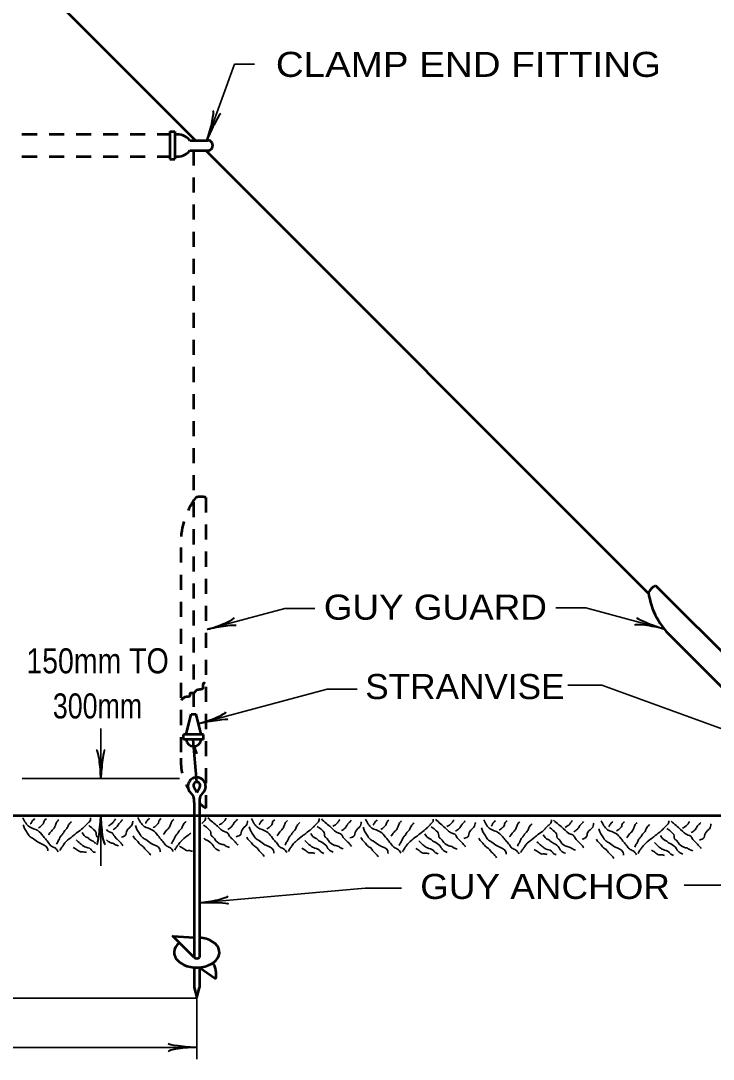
# Model space of a CAD drawing. Extents: x 14808 to 15663, y 10944 to 11488.
# Drawn here: x 15352 to 15435, y 11248.2 to 11372.5 of the extents above; entities that cross this region are included whole.
import ezdxf
from ezdxf.enums import TextEntityAlignment as Align

# ---------------------------------------------------------------- set-up
doc = ezdxf.new("R2010")
doc.units = 0
doc.header["$LTSCALE"] = 1.2
doc.linetypes.add('SHORT_DASHED', pattern=[2.7, 1.5, -1.2])
doc.layers.add('1', color=7, linetype='Continuous', lineweight=53)

msp = doc.modelspace()

# ---------------------------------------------------------------- linework, layer by layer
at = {"layer": '1'}
for p, q in [((15299.491, 11431.696), (15372.897, 11358.29)), ((15369.889, 11359.262), (15369.889, 11355.963)), ((15369.889, 11359.262), (15370.489, 11359.262)), ((15370.489, 11359.262), (15370.489, 11355.963)), ((15372.303, 11358.217), (15374.389, 11358.213)), ((15372.303, 11357.004), (15374.483, 11357.013)), ((15374.159, 11357.028), (15427.228, 11303.959)), ((15369.889, 11355.963), (15370.489, 11355.963)), ((15428.058, 11304.925), (15454.362, 11278.621)), ((15430.179, 11298.561), (15447.998, 11280.742)), ((15371.835, 11287.093), (15372.435, 11289.493)), ((15372.435, 11289.493), (15373.034, 11289.493)), ((15373.635, 11287.093), (15373.034, 11289.493)), ((15373.934, 11287.093), (15371.535, 11287.093)), ((15371.535, 11286.493), (15371.535, 11287.093)), ((15373.934, 11286.493), (15373.934, 11287.093)), ((15373.934, 11286.493), (15371.535, 11286.493)), ((15373.128, 11281.388), (15372.681, 11286.489)), ((15372.753, 11285.671), (15373.087, 11284.754)), ((15373.118, 11280.128), (15372.758, 11280.752)), ((15373.118, 11280.128), (15373.478, 11280.752)), ((15373.427, 11278.945), (15373.427, 11272.659)), ((15267.529, 11277.361), (15491.726, 11277.361)), ((15373.427, 11272.61), (15373.427, 11260.378)), ((15373.427, 11259.178), (15373.427, 11256.778)), ((15373.427, 11259.178), (15375.393, 11257.801))]:
    msp.add_line(p, q, dxfattribs=at)
at = {"layer": '1', "linetype": 'SHORT_DASHED'}
for p, q in [((15297.1, 11358.975), (15369.889, 11358.975)), ((15372.735, 11357.006), (15372.735, 11289.493)), ((15297.101, 11356.276), (15369.889, 11356.276)), ((15374.202, 11315.454), (15374.202, 11278.254)), ((15371.203, 11309.454), (15371.203, 11284.254))]:
    msp.add_line(p, q, dxfattribs=at)
at = {"layer": '1', "lineweight": 35}
for p, q in [((15383.661, 11302.157), (15374.388, 11299.673)), ((15383.661, 11302.157), (15387.261, 11302.157)), ((15419.732, 11302.225), (15416.132, 11302.225)), ((15429.004, 11299.741), (15419.732, 11302.225)), ((15388.739, 11292.497), (15373.398, 11288.387)), ((15388.739, 11292.497), (15392.313, 11292.497)), ((15421.629, 11293.001), (15417.559, 11293.001)), ((15445.843, 11284.188), (15421.629, 11293.001)), ((15361.621, 11281.805), (15361.621, 11287.805)), ((15371.052, 11281.805), (15352.19, 11281.805)), ((15361.621, 11277.361), (15361.621, 11271.361)), ((15393.276, 11268.659), (15373.427, 11266.923)), ((15393.276, 11268.659), (15397.622, 11268.659)), ((15436.634, 11269.019), (15431.481, 11269.019)), ((15373.088, 11255.52), (15350.104, 11255.52)), ((15373.106, 11255.474), (15373.106, 11248.194)), ((15296.404, 11249.616), (15373.132, 11249.616))]:
    msp.add_line(p, q, dxfattribs=at)
msp.add_lwpolyline([(15374.36, 11358.317), (15377.643, 11367.338), (15380.043, 11367.338)], dxfattribs=at)
at = {"layer": '1'}
for points in [[(15372.8, 11278.945), (15372.8, 11272.61), (15372.8, 11260.378)], [(15372.8, 11260.378), (15370.254, 11262.923), (15372.784, 11262.764)], [(15372.8, 11259.178), (15372.8, 11256.778), (15373.113, 11255.578), (15373.427, 11256.778)]]:
    msp.add_lwpolyline(points, dxfattribs=at)
for centre, radius, start, end in [((15370.75, 11356.916), 2.026, 39.94521, 97.50756), ((15374.436, 11357.613), 0.602, 265.53287, 94.46714), ((15370.75, 11358.306), 2.026, 262.49244, 320.05479), ((15428.876, 11303.258), 1.858, 116.15616, 153.84384), ((15436.389, 11305.462), 9.284, 188.58388, 228.01714), ((15372.734, 11286.575), 0.904, 185.20411, 354.79589), ((15373.119, 11280.881), 1.064, 337.37581, 202.62419), ((15373.118, 11280.968), 0.42, 328.9871, 211.0129), ((15375.089, 11281.959), 3.305, 206.74116, 223.96028), ((15371.043, 11279.091), 1.762, 355.24577, 19.00426), ((15375.184, 11279.091), 1.762, 160.99574, 184.75423), ((15371.61, 11281.661), 2.761, 313.69833, 334.49446), ((15373.113, 11260.715), 0.461, 227.04039, 312.95961), ((15372.947, 11258.344), 2.506, 347.48706, 33.42981)]:
    msp.add_arc(centre, radius, start, end, dxfattribs=at)
at = {"layer": '1', "linetype": 'SHORT_DASHED'}
for centre, radius, start, end in [((15373.602, 11313.696), 1.858, 71.15616, 108.84384), ((15380.473, 11309.943), 9.284, 143.58388, 183.01714), ((15378.192, 11283.999), 6.994, 177.90975, 209.56823), ((15378.192, 11283.999), 6.994, 227.0576, 235.22035)]:
    msp.add_arc(centre, radius, start, end, dxfattribs=at)
at = {"layer": '1', "lineweight": 40}
for centre, major_axis, ratio, start_param, end_param in [((15374.496, 11359.661), (-0.557, -2.078), 0.122415, 0.8963533, 3.1415927), ((15375.058, 11359.494), (0.919, 1.909), 0.07063, 6.2823074, 8.5597026), ((15375.567, 11300.332), (-2.021, -0.736), 0.122415, 0.8963533, 3.1415927), ((15427.771, 11300.334), (-1.981, 0.749), 0.07063, 6.2823074, 8.5597026), ((15375.753, 11299.776), (2.09, 0.342), 0.07063, 6.2823074, 8.5597026), ((15427.654, 11299.759), (2.118, -0.374), 0.122415, 0.8963533, 3.1415927), ((15374.577, 11289.046), (-2.021, -0.736), 0.122415, 0.8963533, 3.1415927), ((15374.763, 11288.489), (2.09, 0.342), 0.07063, 6.2823074, 8.5597026), ((15361.289, 11283.114), (0.187, -2.143), 0.122415, 0.8963533, 3.1415927), ((15361.875, 11283.15), (0.211, 2.108), 0.07063, 6.2823074, 8.5597026), ((15361.367, 11276.017), (-0.211, -2.108), 0.07063, 6.2823074, 8.5597026), ((15361.952, 11276.052), (-0.187, 2.143), 0.122415, 0.8963533, 3.1415927), ((15374.703, 11267.367), (-2.118, -0.373), 0.122415, 0.8963533, 3.1415927), ((15374.789, 11266.787), (2.118, -0.026), 0.07063, 6.2823074, 8.5597026), ((15371.787, 11249.87), (2.108, -0.211), 0.07063, 3.1407148, 5.41811), ((15371.822, 11249.284), (2.143, 0.187), 0.122415, 0.8963533, 3.1415927)]:
    msp.add_ellipse(centre, major_axis=major_axis, ratio=ratio, start_param=start_param, end_param=end_param, dxfattribs=at)
at = {"layer": '1'}
msp.add_ellipse((15373.113, 11260.978), major_axis=(-2.714, 0), ratio=0.663245, start_param=5.5824837, end_param=10.8796755, dxfattribs=at)
msp.add_spline([(15374.123, 11293.2), (15373.921, 11293.218), (15373.842, 11292.771), (15373.792, 11292.539), (15373.376, 11292.444), (15372.918, 11292.214), (15372.726, 11292.034), (15372.301, 11291.994), (15372.274, 11291.688), (15371.871, 11291.572), (15371.521, 11291.447), (15371.238, 11291.148)], degree=3, dxfattribs=at)
at = {"layer": '1', "lineweight": 35}
for points in [[(15352.297, 11277.1), (15353.065, 11276.025), (15354.063, 11275.565), (15354.677, 11274.95), (15354.984, 11274.567), (15355.368, 11274.106), (15355.675, 11273.722), (15356.136, 11273.492), (15356.52, 11273.031)], [(15353.679, 11277.014), (15353.564, 11276.861), (15353.526, 11276.861), (15353.449, 11276.784), (15353.257, 11276.438), (15353.219, 11276.362)], [(15360.397, 11277.1), (15360.397, 11276.947), (15360.32, 11276.716), (15360.167, 11276.563), (15360.013, 11276.409), (15359.706, 11276.102), (15359.476, 11275.872), (15358.785, 11275.334), (15358.401, 11275.027), (15357.633, 11274.413), (15357.326, 11274.106), (15357.172, 11273.876), (15356.942, 11273.569), (15356.712, 11273.185)], [(15366.059, 11277.15), (15366.827, 11276.075), (15367.825, 11275.614), (15368.439, 11275), (15368.746, 11274.616), (15369.13, 11274.155), (15369.437, 11273.772), (15369.898, 11273.541), (15370.281, 11273.081)], [(15367.441, 11277.064), (15367.326, 11276.91), (15367.287, 11276.91), (15367.21, 11276.833), (15367.018, 11276.488), (15366.98, 11276.411)], [(15368.861, 11277.025), (15368.631, 11276.833), (15368.554, 11276.641), (15368.477, 11276.411), (15368.324, 11276.257), (15368.247, 11276.181), (15367.901, 11275.912)], [(15374.158, 11277.15), (15374.158, 11276.996), (15374.082, 11276.766), (15373.928, 11276.612), (15373.775, 11276.459), (15373.751, 11276.435)], [(15374.427, 11277.111), (15375.041, 11276.574), (15375.579, 11276.113), (15376.5, 11275.422), (15376.73, 11275.345), (15376.961, 11275.038), (15377.345, 11274.578), (15377.805, 11274.117), (15378.035, 11273.81)], [(15375.809, 11276.257), (15376.347, 11276.641), (15376.462, 11276.795), (15376.654, 11277.064)], [(15352.326, 11276.28), (15352.479, 11275.819), (15352.786, 11275.32), (15353.17, 11274.821), (15353.554, 11274.591), (15354.206, 11274.13), (15355.243, 11273.439), (15355.281, 11273.132)], [(15355.099, 11276.976), (15354.869, 11276.784), (15354.792, 11276.592), (15354.716, 11276.362), (15354.562, 11276.208), (15354.485, 11276.131), (15354.14, 11275.862)], [(15356.597, 11276.861), (15356.366, 11276.63), (15356.213, 11276.246), (15356.021, 11275.863), (15355.598, 11275.402), (15355.445, 11275.172), (15355.368, 11275.056)], [(15358.094, 11276.63), (15357.748, 11276.246), (15357.556, 11275.824), (15357.249, 11275.479), (15357.019, 11275.133), (15356.788, 11274.864), (15356.673, 11274.596), (15356.52, 11274.327), (15356.328, 11273.943)], [(15360.167, 11276.169), (15360.397, 11276.016), (15360.627, 11275.824), (15361.049, 11275.287), (15361.088, 11274.941), (15361.297, 11274.758)], [(15362.543, 11276.158), (15363.08, 11276.542), (15363.195, 11276.696), (15363.387, 11276.965)], [(15363.084, 11275.671), (15363.506, 11275.978), (15363.775, 11276.362), (15363.852, 11276.477), (15364.005, 11276.63), (15364.236, 11276.899)], [(15364.082, 11274.788), (15364.619, 11275.095), (15364.696, 11275.44), (15365.195, 11276.054), (15365.349, 11276.246), (15365.426, 11276.553), (15365.464, 11276.707)], [(15365.79, 11276.181), (15365.944, 11275.72), (15366.251, 11275.221), (15366.635, 11274.722), (15367.018, 11274.492), (15367.671, 11274.031), (15368.708, 11273.34), (15368.746, 11273.033)], [(15370.358, 11276.91), (15370.128, 11276.68), (15369.974, 11276.296), (15369.782, 11275.912), (15369.36, 11275.451), (15369.207, 11275.221), (15369.13, 11275.106)], [(15371.855, 11276.68), (15371.51, 11276.296), (15371.318, 11275.873), (15371.011, 11275.528), (15370.78, 11275.183), (15370.55, 11274.914), (15370.435, 11274.645), (15370.281, 11274.376), (15370.089, 11273.993)], [(15373.928, 11276.219), (15374.158, 11276.066), (15374.389, 11275.874), (15374.811, 11275.336), (15374.849, 11274.991), (15375.157, 11274.722), (15375.272, 11274.53), (15376.039, 11273.954), (15376.5, 11273.801), (15376.615, 11273.724), (15377.037, 11273.532)], [(15376.846, 11275.72), (15377.268, 11276.027), (15377.537, 11276.411), (15377.613, 11276.526), (15377.767, 11276.68), (15377.997, 11276.948)], [(15377.844, 11274.837), (15378.381, 11275.144), (15378.458, 11275.49), (15378.957, 11276.104), (15379.11, 11276.296), (15379.187, 11276.603), (15379.226, 11276.757)], [(15379.403, 11276.032), (15379.557, 11275.572), (15379.864, 11275.073), (15380.248, 11274.574), (15380.632, 11274.343), (15381.284, 11273.882), (15382.321, 11273.192), (15382.359, 11272.884)], [(15379.672, 11277.001), (15380.44, 11275.926), (15381.438, 11275.466), (15382.052, 11274.851), (15382.359, 11274.468), (15382.743, 11274.007), (15383.05, 11273.623), (15383.511, 11273.393), (15383.895, 11272.932)], [(15381.054, 11276.915), (15380.939, 11276.762), (15380.9, 11276.762), (15380.824, 11276.685), (15380.632, 11276.339), (15380.593, 11276.263)], [(15382.474, 11276.877), (15382.244, 11276.685), (15382.167, 11276.493), (15382.09, 11276.263), (15381.937, 11276.109), (15381.86, 11276.032), (15381.514, 11275.763)], [(15383.971, 11276.762), (15383.741, 11276.531), (15383.587, 11276.147), (15383.395, 11275.764), (15382.973, 11275.303), (15382.82, 11275.073), (15382.743, 11274.957)], [(15385.468, 11276.531), (15385.123, 11276.147), (15384.931, 11275.725), (15384.624, 11275.38), (15384.394, 11275.034), (15384.163, 11274.765), (15384.048, 11274.497), (15383.894, 11274.228), (15383.703, 11273.844)], [(15387.772, 11277.001), (15387.772, 11276.848), (15387.695, 11276.617), (15387.541, 11276.464), (15387.388, 11276.31), (15387.081, 11276.003), (15386.85, 11275.773), (15386.159, 11275.235), (15385.775, 11274.928), (15385.008, 11274.314), (15384.701, 11274.007), (15384.547, 11273.777), (15384.317, 11273.47), (15384.086, 11273.086)], [(15387.541, 11276.07), (15387.772, 11275.917), (15388.002, 11275.725), (15388.424, 11275.188), (15388.463, 11274.842), (15388.77, 11274.574), (15388.885, 11274.382), (15389.653, 11273.806), (15390.113, 11273.652), (15390.228, 11273.575), (15390.651, 11273.383)], [(15388.04, 11276.963), (15388.654, 11276.425), (15389.192, 11275.965), (15390.113, 11275.274), (15390.343, 11275.197), (15390.574, 11274.89), (15390.958, 11274.429), (15391.418, 11273.969), (15391.649, 11273.661)], [(15389.422, 11276.109), (15389.96, 11276.493), (15390.075, 11276.646), (15390.267, 11276.915)], [(15390.459, 11275.572), (15390.881, 11275.879), (15391.15, 11276.263), (15391.226, 11276.378), (15391.38, 11276.531), (15391.61, 11276.8)], [(15391.457, 11274.689), (15391.994, 11274.996), (15392.071, 11275.341), (15392.57, 11275.955), (15392.723, 11276.147), (15392.8, 11276.454), (15392.839, 11276.608)], [(15393.066, 11275.983), (15393.219, 11275.522), (15393.526, 11275.023), (15393.91, 11274.524), (15394.294, 11274.294), (15394.947, 11273.833), (15395.983, 11273.142), (15396.022, 11272.835)], [(15393.335, 11276.952), (15394.102, 11275.877), (15395.1, 11275.416), (15395.715, 11274.802), (15396.022, 11274.418), (15396.406, 11273.957), (15396.713, 11273.574), (15397.173, 11273.343), (15397.557, 11272.882)], [(15394.716, 11276.866), (15394.601, 11276.712), (15394.563, 11276.712), (15394.486, 11276.635), (15394.294, 11276.29), (15394.256, 11276.213)], [(15396.137, 11276.827), (15395.906, 11276.635), (15395.83, 11276.443), (15395.753, 11276.213), (15395.599, 11276.059), (15395.523, 11275.983), (15395.177, 11275.714)], [(15397.634, 11276.712), (15397.404, 11276.482), (15397.25, 11276.098), (15397.058, 11275.714), (15396.636, 11275.253), (15396.482, 11275.023), (15396.405, 11274.908)], [(15399.131, 11276.482), (15398.785, 11276.098), (15398.594, 11275.676), (15398.286, 11275.33), (15398.056, 11274.985), (15397.826, 11274.716), (15397.711, 11274.447), (15397.557, 11274.178), (15397.365, 11273.795)], [(15401.434, 11276.952), (15401.434, 11276.798), (15401.357, 11276.568), (15401.204, 11276.414), (15401.05, 11276.261), (15400.743, 11275.954), (15400.513, 11275.723), (15399.822, 11275.186), (15399.438, 11274.879), (15398.67, 11274.265), (15398.363, 11273.957), (15398.21, 11273.727), (15397.979, 11273.42), (15397.749, 11273.036)], [(15401.204, 11276.021), (15401.434, 11275.868), (15401.664, 11275.676), (15402.087, 11275.138), (15402.125, 11274.793), (15402.432, 11274.524), (15402.547, 11274.332), (15403.315, 11273.756), (15403.776, 11273.603), (15403.891, 11273.526), (15404.313, 11273.334)], [(15401.703, 11276.913), (15402.317, 11276.376), (15402.854, 11275.915), (15403.776, 11275.224), (15404.006, 11275.147), (15404.236, 11274.84), (15404.62, 11274.38), (15405.081, 11273.919), (15405.311, 11273.612)], [(15403.085, 11276.059), (15403.622, 11276.443), (15403.737, 11276.597), (15403.929, 11276.866)], [(15404.121, 11275.522), (15404.544, 11275.829), (15404.812, 11276.213), (15404.889, 11276.328), (15405.043, 11276.482), (15405.273, 11276.75)], [(15405.119, 11274.639), (15405.657, 11274.946), (15405.734, 11275.292), (15406.233, 11275.906), (15406.386, 11276.098), (15406.463, 11276.405), (15406.501, 11276.559)], [(15407.224, 11275.884), (15407.377, 11275.423), (15407.684, 11274.924), (15408.068, 11274.425), (15408.452, 11274.195), (15409.104, 11273.734), (15410.141, 11273.043), (15410.179, 11272.736)], [(15407.492, 11276.853), (15408.26, 11275.778), (15409.258, 11275.317), (15409.872, 11274.703), (15410.179, 11274.319), (15410.563, 11273.858), (15410.87, 11273.475), (15411.331, 11273.244), (15411.715, 11272.784)], [(15408.874, 11276.767), (15408.759, 11276.613), (15408.721, 11276.613), (15408.644, 11276.536), (15408.452, 11276.191), (15408.414, 11276.114)], [(15410.294, 11276.728), (15410.064, 11276.536), (15409.987, 11276.344), (15409.91, 11276.114), (15409.757, 11275.96), (15409.68, 11275.884), (15409.335, 11275.615)], [(15411.792, 11276.613), (15411.561, 11276.383), (15411.408, 11275.999), (15411.216, 11275.615), (15410.793, 11275.154), (15410.64, 11274.924), (15410.563, 11274.809)], [(15413.289, 11276.383), (15412.943, 11275.999), (15412.751, 11275.577), (15412.444, 11275.231), (15412.214, 11274.886), (15411.983, 11274.617), (15411.868, 11274.348), (15411.715, 11274.079), (15411.523, 11273.696)], [(15415.592, 11276.853), (15415.592, 11276.699), (15415.515, 11276.469), (15415.362, 11276.315), (15415.208, 11276.162), (15414.901, 11275.855), (15414.671, 11275.624), (15413.98, 11275.087), (15413.596, 11274.78), (15412.828, 11274.166), (15412.521, 11273.858), (15412.367, 11273.628), (15412.137, 11273.321), (15411.907, 11272.937)], [(15415.362, 11275.922), (15415.592, 11275.769), (15415.822, 11275.577), (15416.244, 11275.039), (15416.283, 11274.694), (15416.59, 11274.425), (15416.705, 11274.233), (15417.473, 11273.657), (15417.933, 11273.504), (15418.049, 11273.427), (15418.471, 11273.235)], [(15415.861, 11276.814), (15416.475, 11276.277), (15417.012, 11275.816), (15417.933, 11275.125), (15418.164, 11275.048), (15418.394, 11274.741), (15418.778, 11274.281), (15419.239, 11273.82), (15419.469, 11273.513)], [(15417.243, 11275.96), (15417.78, 11276.344), (15417.895, 11276.498), (15418.087, 11276.767)], [(15418.279, 11275.423), (15418.701, 11275.73), (15418.97, 11276.114), (15419.047, 11276.229), (15419.2, 11276.383), (15419.431, 11276.651)], [(15419.277, 11274.54), (15419.814, 11274.847), (15419.891, 11275.193), (15420.39, 11275.807), (15420.544, 11275.999), (15420.621, 11276.306), (15420.659, 11276.46)], [(15421.282, 11275.785), (15421.436, 11275.324), (15421.743, 11274.825), (15422.127, 11274.326), (15422.511, 11274.096), (15423.163, 11273.635), (15424.2, 11272.944), (15424.238, 11272.637)], [(15421.551, 11276.754), (15422.319, 11275.679), (15423.317, 11275.218), (15423.931, 11274.604), (15424.238, 11274.22), (15424.622, 11273.759), (15424.929, 11273.376), (15425.39, 11273.145), (15425.774, 11272.685)], [(15422.933, 11276.668), (15422.818, 11276.514), (15422.779, 11276.514), (15422.703, 11276.437), (15422.511, 11276.092), (15422.472, 11276.015)], [(15424.353, 11276.629), (15424.123, 11276.437), (15424.046, 11276.245), (15423.969, 11276.015), (15423.816, 11275.861), (15423.739, 11275.785), (15423.393, 11275.516)], [(15425.85, 11276.514), (15425.62, 11276.284), (15425.466, 11275.9), (15425.274, 11275.516), (15424.852, 11275.055), (15424.699, 11274.825), (15424.622, 11274.71)], [(15427.347, 11276.284), (15427.002, 11275.9), (15426.81, 11275.478), (15426.503, 11275.132), (15426.273, 11274.787), (15426.042, 11274.518), (15425.927, 11274.249), (15425.773, 11273.98), (15425.582, 11273.597)], [(15429.651, 11276.754), (15429.651, 11276.6), (15429.574, 11276.37), (15429.42, 11276.216), (15429.267, 11276.063), (15428.96, 11275.756), (15428.729, 11275.525), (15428.038, 11274.988), (15427.654, 11274.681), (15426.887, 11274.067), (15426.58, 11273.759), (15426.426, 11273.529), (15426.196, 11273.222), (15425.965, 11272.838)], [(15429.42, 11275.823), (15429.651, 11275.669), (15429.881, 11275.478), (15430.303, 11274.94), (15430.342, 11274.595), (15430.649, 11274.326), (15430.764, 11274.134), (15431.532, 11273.558), (15431.992, 11273.405), (15432.107, 11273.328), (15432.53, 11273.136)], [(15429.919, 11276.715), (15430.533, 11276.178), (15431.071, 11275.717), (15431.992, 11275.026), (15432.222, 11274.949), (15432.453, 11274.642), (15432.837, 11274.182), (15433.297, 11273.721), (15433.528, 11273.414)], [(15431.301, 11275.861), (15431.839, 11276.245), (15431.954, 11276.399), (15432.146, 11276.668)], [(15432.338, 11275.324), (15432.76, 11275.631), (15433.029, 11276.015), (15433.105, 11276.13), (15433.259, 11276.284), (15433.489, 11276.552)], [(15433.336, 11274.441), (15433.873, 11274.748), (15433.95, 11275.094), (15434.449, 11275.708), (15434.602, 11275.9), (15434.679, 11276.207), (15434.718, 11276.361)], [(15359.399, 11275.325), (15359.975, 11274.749), (15360.09, 11274.711), (15360.205, 11274.596), (15360.704, 11274.289), (15361.01, 11274.021)], [(15362.303, 11275.699), (15362.738, 11275.373), (15362.969, 11275.296), (15363.199, 11274.989), (15363.583, 11274.528), (15364.044, 11274.068), (15364.274, 11273.76)], [(15365.483, 11274.952), (15365.637, 11274.684), (15365.944, 11274.377), (15366.328, 11273.916), (15366.673, 11273.686), (15366.98, 11273.302), (15367.287, 11272.995), (15367.594, 11272.611)], [(15372.388, 11275.257), (15372.162, 11275.077), (15371.395, 11274.462), (15371.087, 11274.155), (15370.934, 11273.925), (15370.704, 11273.618), (15370.473, 11273.234)], [(15373.941, 11274.671), (15373.967, 11274.645), (15374.466, 11274.338), (15375.08, 11273.801), (15375.272, 11273.494), (15375.847, 11273.148)], [(15379.096, 11274.804), (15379.25, 11274.535), (15379.557, 11274.228), (15379.941, 11273.767), (15380.286, 11273.537), (15380.593, 11273.153), (15380.9, 11272.846), (15381.207, 11272.462)], [(15386.774, 11275.226), (15387.349, 11274.65), (15387.464, 11274.612), (15387.58, 11274.497), (15388.079, 11274.19), (15388.693, 11273.652), (15388.885, 11273.345), (15389.461, 11273)], [(15392.759, 11274.754), (15392.912, 11274.486), (15393.219, 11274.178), (15393.603, 11273.718), (15393.949, 11273.488), (15394.256, 11273.104), (15394.563, 11272.797), (15394.87, 11272.413)], [(15400.436, 11275.177), (15401.012, 11274.601), (15401.127, 11274.562), (15401.242, 11274.447), (15401.741, 11274.14), (15402.355, 11273.603), (15402.547, 11273.296), (15403.123, 11272.95)], [(15406.916, 11274.655), (15407.07, 11274.387), (15407.377, 11274.079), (15407.761, 11273.619), (15408.106, 11273.389), (15408.414, 11273.005), (15408.721, 11272.698), (15409.028, 11272.314)], [(15414.594, 11275.078), (15415.17, 11274.502), (15415.285, 11274.463), (15415.4, 11274.348), (15415.899, 11274.041), (15416.513, 11273.504), (15416.705, 11273.197), (15417.281, 11272.851)], [(15420.975, 11274.556), (15421.129, 11274.288), (15421.436, 11273.98), (15421.82, 11273.52), (15422.165, 11273.29), (15422.472, 11272.906), (15422.779, 11272.599), (15423.086, 11272.215)], [(15428.653, 11274.979), (15429.228, 11274.403), (15429.343, 11274.364), (15429.459, 11274.249), (15429.958, 11273.942), (15430.572, 11273.405), (15430.764, 11273.098), (15431.34, 11272.752)], [(15358.324, 11273.559), (15358.593, 11273.406), (15359.092, 11273.06), (15359.168, 11273.022), (15359.399, 11273.022), (15359.898, 11272.945)], [(15358.669, 11274.48), (15359.168, 11274.02), (15359.36, 11273.866), (15359.706, 11273.636), (15360.397, 11273.367), (15360.627, 11273.099), (15360.973, 11272.945)], [(15362.322, 11274.453), (15362.723, 11274.152), (15363.184, 11273.999), (15363.299, 11273.922), (15363.721, 11273.73)], [(15371.046, 11273.708), (15371.315, 11273.554), (15371.814, 11273.209), (15371.89, 11273.17), (15372.121, 11273.17), (15372.62, 11273.094)], [(15385.699, 11273.46), (15385.967, 11273.307), (15386.466, 11272.961), (15386.543, 11272.923), (15386.774, 11272.923), (15387.273, 11272.846)], [(15386.044, 11274.382), (15386.543, 11273.921), (15386.735, 11273.767), (15387.081, 11273.537), (15387.772, 11273.268), (15388.002, 11273), (15388.347, 11272.846)], [(15399.361, 11273.411), (15399.63, 11273.257), (15400.129, 11272.912), (15400.206, 11272.873), (15400.436, 11272.873), (15400.935, 11272.797)], [(15399.707, 11274.332), (15400.206, 11273.871), (15400.398, 11273.718), (15400.743, 11273.488), (15401.434, 11273.219), (15401.664, 11272.95), (15402.01, 11272.797)], [(15413.519, 11273.312), (15413.788, 11273.158), (15414.287, 11272.813), (15414.363, 11272.774), (15414.594, 11272.774), (15415.093, 11272.698)], [(15413.864, 11274.233), (15414.363, 11273.772), (15414.555, 11273.619), (15414.901, 11273.389), (15415.592, 11273.12), (15415.822, 11272.851), (15416.168, 11272.698)], [(15427.923, 11274.134), (15428.422, 11273.673), (15428.614, 11273.52), (15428.96, 11273.29), (15429.651, 11273.021), (15429.881, 11272.752), (15430.226, 11272.599)], [(15427.578, 11273.213), (15427.846, 11273.059), (15428.345, 11272.714), (15428.422, 11272.675), (15428.653, 11272.675), (15429.151, 11272.599)]]:
    msp.add_spline(points, degree=3, dxfattribs=at)

# ---------------------------------------------------------------- texts
at = {"layer": '1'}
for s, width, p in [('CLAMP END FITTING', 1.15, (15382.586, 11365.82)), ('STRANVISE', 1.05, (15393.293, 11291.318))]:
    msp.add_text(s, height=3, dxfattribs=dict(at, width=width)).set_placement(p)
for s, width, p in [('GUY GUARD', 1.1, (15401.694, 11300.825)), ('150mm TO', 0.85, (15361.229, 11294.399)), ('300mm', 0.8, (15361.229, 11288.999)), ('GUY ANCHOR', 1.1, (15414.835, 11267.384))]:
    msp.add_text(s, height=3, dxfattribs=dict(at, width=width)).set_placement(p, align=Align.CENTER)

doc.saveas('drawing.dxf')
